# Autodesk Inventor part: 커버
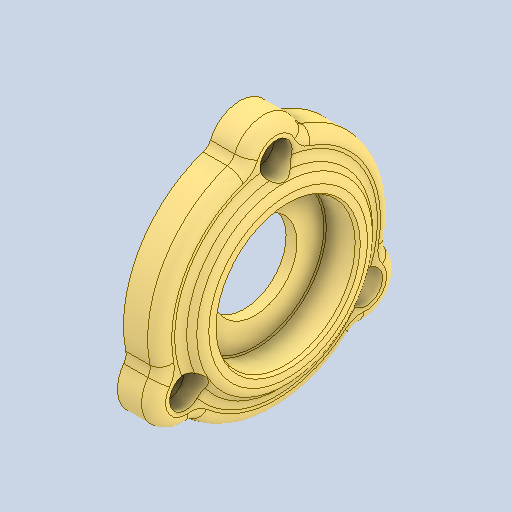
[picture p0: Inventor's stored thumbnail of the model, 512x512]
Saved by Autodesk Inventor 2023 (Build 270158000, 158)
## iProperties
Created: 2026-03
Part Number: 커버
Material: 알루미늄 6061
Document SubType Name: Modeling
Designer: 4강의실
Density: 2.7 g/cm^3
Appearance: 기본값
Author: jhkim
Sending System: Autodesk Inventor 2026
Preprocessor: ST-DEVELOPER v20.1
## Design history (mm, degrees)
feature "솔리드1"
node "솔리드2"
